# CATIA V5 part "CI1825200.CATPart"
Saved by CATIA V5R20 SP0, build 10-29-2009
Part number: CI1825200
Bounding box of the stored display mesh (mm): x -24 to 24, y -19.337 to 234.5, z -31.667 to 27.272
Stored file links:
  C:\Users\Raffaele\Desktop\3D X SITO CF\BOLEX\19-INCLINED ASSEMBLY REF_CI\CI1825200.CATPart

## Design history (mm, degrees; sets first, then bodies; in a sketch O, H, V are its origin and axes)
Set1
  DatumSurface1 to DatumSurface16 "MANIFOLD_SOLID_BREP #393"
  DatumSurface17 to DatumSurface39 "MANIFOLD_SOLID_BREP #1138"
Body1 (main body)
